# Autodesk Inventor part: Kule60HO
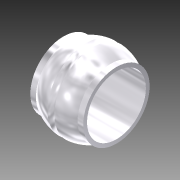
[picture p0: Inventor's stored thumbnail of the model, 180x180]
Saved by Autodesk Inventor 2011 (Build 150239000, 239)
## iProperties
Created: 2010-11
Document SubType Name: Modeling
Designer: tribel
Density: 1 g/cm^3
Author: tribel
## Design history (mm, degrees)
sketch "Sketch1"
  geometry: L1 (-37.8, 0)-(37.8, 0) reference; L2 (0, -11.928)-(0, 71.57) reference; L3 (-27, 33.85)-(-21.236, 33.85); L4 (-27, 33.85)-(-27, 0); L5 (-3.5, 0)-(-3.5, 39.806); L6 (-27, 30)-(-3.5, 30); L7 (27, 33.85)-(21.236, 33.85); L8 (27, 33.85)-(27, 0); L9 (27, 30)-(3.5, 30); L10 (3.5, 0)-(3.5, 39.806); L11 (-3.5, 30)-(3.5, 30); A1 r 20.142 centre (0, 59.642) between (-3.5, 39.806) and (3.5, 39.806); A2 r 39.96 centre (0, 0) between (21.236, 33.85) and (3.5, 39.806); A3 r 39.96 centre (0, 0) between (-3.5, 39.806) and (-21.236, 33.85)
  constraints: 18 end point, 7 symmetric about line, 6 point on circle, 6 point on line, 4 perpendicular, 3 centre point, 1 parallel
  dimensions: "d1" = 27 distance between parallel lines of L4 L2; "d2" = 3.5 distance between parallel lines of L5 L2; "d3" = 67.7 diameter of L3 L1; "d4" = 79 dimension on A1 L1; "d5" = 60 diameter of L9 L1; "d7" = 39.96 radius of A3
revolve "Revolution1" sketch "Sketch1" stored, may be unused: angle "d8" = 90 deg
body "Solid1"
other parameters: "d0" = 65.92, "d6" = 32.96
